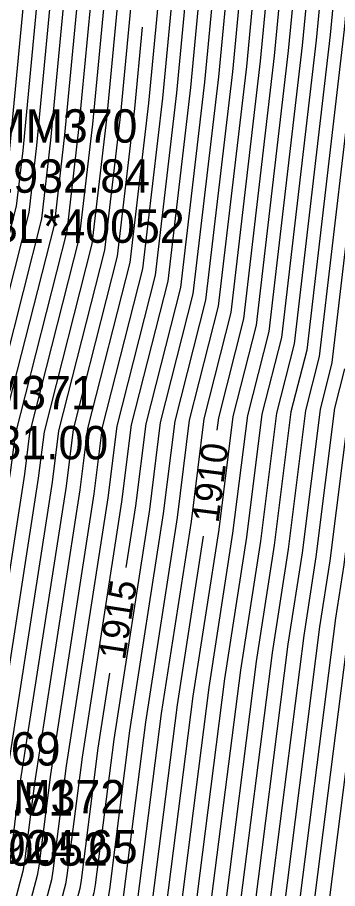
# Model space of a CAD drawing. Extents: x 1004378 to 1005103, y 553854 to 554288.
# Drawn here: x 1004966.5 to 1004990.4, y 553915.8 to 553981 of the extents above; entities that cross this region are included whole.
import ezdxf

# ---------------------------------------------------------------- set-up
doc = ezdxf.new("R2010")
doc.units = 0
for name, color, linetype in [('DTM Contours Major', 7, 'Continuous'), ('DTM Contours Major Text', 7, 'Continuous'), ('DTM Contours Minor', 7, 'Continuous'), ('Exist DTM Breakline Cogo Comment', 7, 'Continuous'), ('Exist DTM Breakline Cogo Elevation', 7, 'Continuous'), ('Exist DTM Breakline Cogo Number', 7, 'Continuous')]:
    doc.layers.add(name, color=color, linetype=linetype)

msp = doc.modelspace()

# ---------------------------------------------------------------- linework, layer by layer
at = {"layer": 'DTM Contours Major'}
for points in [[(1004990.518, 554049.324), (1004989.746, 554042.345), (1004988.945, 554039.431), (1004989.353, 554038.463), (1004988.859, 554029.118), (1004988.632, 554018.987), (1004987.49, 553995.198), (1004986.608, 553987.828), (1004985.684, 553978.101), (1004983.38, 553958.418), (1004981.497, 553951.011), (1004981.379, 553950.073)], [(1004984.132, 554039.131), (1004983.915, 554035.018), (1004983.493, 554016.156), (1004982.562, 553996.779), (1004981.844, 553990.776), (1004980.452, 553976.132), (1004978.652, 553960.758), (1004976.062, 553950.567), (1004975.294, 553944.427), (1004974.577, 553939.804)], [(1004992.875, 554003.128), (1004992.418, 553993.617), (1004991.372, 553984.881), (1004990.915, 553980.071), (1004988.107, 553956.077), (1004986.932, 553951.455), (1004985.684, 553941.478), (1004984.331, 553932.757), (1004981.805, 553912.854), (1004981.751, 553912.525), (1004979.522, 553904.173)], [(1004971.479, 553987.875), (1004969.989, 553972.194), (1004969.198, 553965.438), (1004965.192, 553949.68), (1004964.904, 553947.376), (1004960.748, 553920.578), (1004960.368, 553920.099), (1004959.949, 553919.572), (1004959.874, 553919.536), (1004954.889, 553917.367), (1004952.025, 553915.484), (1004933.597, 553906.315), (1004932.685, 553906.503)], [(1004975.8, 553980.258), (1004975.22, 553974.163), (1004973.925, 553963.098), (1004970.627, 553950.123), (1004970.099, 553945.901), (1004966.549, 553923.013), (1004965.932, 553918.15), (1004965.808, 553917.384), (1004962.695, 553905.72), (1004954.669, 553902.046), (1004953.262, 553901.433), (1004941.713, 553893.841)], [(1004995.335, 553975.107), (1004992.834, 553953.737), (1004992.367, 553951.898), (1004990.879, 553940.003), (1004990.259, 553936.005), (1004987.096, 553911.089), (1004987.066, 553910.906), (1004985.268, 553904.169), (1004980.322, 553886.217), (1004977.192, 553877.08)], [(1004980.362, 553942.139), (1004978.404, 553929.509), (1004976.514, 553914.62), (1004976.437, 553914.145), (1004971.786, 553896.718), (1004970.051, 553890.42), (1004965.256, 553876.423), (1004947.497, 553866.765), (1004945.875, 553865.882)], [(1004973.351, 553931.899), (1004972.477, 553926.261), (1004971.223, 553916.385), (1004971.123, 553915.765), (1004965.045, 553892.992), (1004964.916, 553892.521), (1004964.557, 553891.474), (1004961.933, 553890.047), (1004946.37, 553881.961), (1004940.591, 553878.151), (1004931.906, 553872.425), (1004932.715, 553870.481)]]:
    msp.add_lwpolyline(points, dxfattribs=at)
at = {"layer": 'DTM Contours Minor'}
for points in [[(1004972.981, 554045.52), (1004972.185, 554009.926), (1004971.721, 554000.256), (1004971.362, 553997.261), (1004968.942, 553971.8), (1004968.253, 553965.906), (1004964.105, 553949.591), (1004963.865, 553947.671), (1004960.401, 553925.336), (1004957.491, 553921.673), (1004957.35, 553921.495), (1004957.063, 553921.358), (1004955.215, 553920.554), (1004954.153, 553919.855), (1004932.16, 553908.913), (1004916.353, 553912.182), (1004913.842, 553914.186), (1004913.087, 553911.609), (1004912.621, 553908.909), (1004907.637, 553886.746), (1004907.279, 553884.335), (1004906.612, 553883.292), (1004908.282, 553879.28)], [(1004975.015, 554045.638), (1004974.241, 554011.059), (1004973.692, 553999.624), (1004973.268, 553996.082), (1004971.035, 553972.588), (1004970.143, 553964.97), (1004966.279, 553949.768), (1004965.943, 553947.081), (1004961.807, 553920.414), (1004961.699, 553919.562), (1004961.557, 553918.68), (1004961.124, 553917.06), (1004960.01, 553916.55), (1004954.564, 553914.18), (1004949.897, 553911.112), (1004935.034, 553903.717), (1004920.298, 553906.764), (1004913.738, 553897.346), (1004910.842, 553884.469), (1004910.705, 553883.545), (1004910.449, 553883.146), (1004912.725, 553877.68)], [(1004976.003, 554044.458), (1004975.269, 554011.625), (1004974.678, 553999.308), (1004974.221, 553995.492), (1004972.081, 553972.981), (1004971.089, 553964.502), (1004967.366, 553949.857), (1004966.982, 553946.786), (1004962.993, 553921.064), (1004962.757, 553919.209), (1004962.62, 553918.356), (1004961.517, 553914.225), (1004958.675, 553912.924), (1004954.239, 553910.994), (1004947.768, 553906.74), (1004936.47, 553901.118), (1004925.269, 553903.435), (1004913.007, 553885.833), (1004912.444, 553883.33), (1004912.418, 553883.151), (1004912.368, 553883.073), (1004914.946, 553876.88)], [(1004976.992, 554043.278), (1004976.297, 554012.192), (1004975.663, 553998.992), (1004975.174, 553994.903), (1004973.128, 553973.375), (1004972.034, 553964.034), (1004968.453, 553949.946), (1004968.021, 553946.491), (1004964.178, 553921.714), (1004963.816, 553918.856), (1004963.683, 553918.032), (1004961.91, 553911.39), (1004957.339, 553909.298), (1004953.913, 553907.807), (1004945.64, 553902.368), (1004937.907, 553898.52), (1004930.24, 553900.106), (1004920.136, 553885.602), (1004914.696, 553882.016), (1004917.167, 553876.081)], [(1004977.981, 554042.098), (1004977.325, 554012.758), (1004976.649, 553998.676), (1004976.126, 553994.313), (1004974.174, 553973.769), (1004972.98, 553963.566), (1004969.54, 553950.035), (1004969.06, 553946.196), (1004965.364, 553922.363), (1004964.874, 553918.503), (1004964.745, 553917.708), (1004962.303, 553908.555), (1004956.004, 553905.672), (1004953.588, 553904.62), (1004943.512, 553897.997), (1004939.343, 553895.922), (1004935.21, 553896.777), (1004929.764, 553888.959), (1004917.155, 553880.646), (1004919.388, 553875.281)], [(1004971.881, 554041.705), (1004971.157, 554009.36), (1004970.735, 554000.573), (1004970.409, 553997.85), (1004967.896, 553971.406), (1004967.307, 553966.374), (1004963.018, 553949.502), (1004962.826, 553947.966), (1004960.054, 553930.094), (1004956.322, 553925.395), (1004955.382, 553924.012), (1004954.895, 553923.733), (1004952.275, 553922.234), (1004930.724, 553911.511), (1004918.442, 553914.051), (1004912.975, 553918.414), (1004911.33, 553912.804), (1004910.317, 553906.926), (1004906.034, 553887.884), (1004905.566, 553884.73), (1004904.694, 553883.365), (1004906.061, 553880.08)], [(1004979.959, 554039.738), (1004979.381, 554013.891), (1004978.62, 553998.043), (1004978.032, 553993.134), (1004976.267, 553974.557), (1004974.871, 553962.63), (1004971.714, 553950.212), (1004971.138, 553945.606), (1004967.735, 553923.663), (1004966.99, 553917.797), (1004966.871, 553917.06), (1004963.088, 553902.885), (1004953.334, 553898.42), (1004952.937, 553898.247), (1004949.019, 553895.671), (1004940.949, 553890.351), (1004922.072, 553877.905), (1004923.831, 553873.681)], [(1004988.333, 554039.04), (1004987.87, 554030.298), (1004987.604, 554018.421), (1004986.505, 553995.514), (1004985.655, 553988.418), (1004984.637, 553977.708), (1004982.434, 553958.886), (1004980.41, 553950.922), (1004979.45, 553943.247), (1004977.219, 553928.86), (1004975.456, 553914.973), (1004975.374, 553914.469), (1004970.438, 553895.973), (1004969.024, 553890.84), (1004965.116, 553879.433), (1004942.966, 553867.387), (1004942.363, 553867.059)], [(1004980.948, 554038.558), (1004980.409, 554014.457), (1004979.606, 553997.727), (1004978.985, 553992.545), (1004977.313, 553974.951), (1004975.816, 553962.162), (1004972.801, 553950.301), (1004972.177, 553945.311), (1004968.92, 553924.312), (1004968.048, 553917.444), (1004967.934, 553916.736), (1004963.481, 553900.05), (1004955.023, 553896.178), (1004951.726, 553894.465), (1004940.859, 553887.301), (1004924.53, 553876.535), (1004926.052, 553872.881)], [(1004970.78, 554037.89), (1004970.129, 554008.794), (1004969.75, 554000.889), (1004969.456, 553998.44), (1004966.85, 553971.012), (1004966.362, 553966.842), (1004961.931, 553949.413), (1004961.787, 553948.261), (1004959.707, 553934.852), (1004956.907, 553931.326), (1004954.06, 553927.139), (1004953.648, 553926.903), (1004944.652, 553921.754), (1004929.287, 553914.109), (1004920.531, 553915.92), (1004912.107, 553922.642), (1004909.573, 553913.998), (1004908.012, 553904.943), (1004904.431, 553889.023), (1004903.852, 553885.125), (1004902.775, 553883.437), (1004903.84, 553880.88)], [(1004990.374, 554037.886), (1004989.848, 554027.938), (1004989.66, 554019.554), (1004988.476, 553994.882), (1004987.561, 553987.239), (1004986.73, 553978.495), (1004984.325, 553957.95), (1004982.584, 553951.1), (1004981.528, 553942.657), (1004979.589, 553930.159), (1004977.572, 553914.267), (1004977.5, 553913.821), (1004973.135, 553897.463), (1004971.078, 553890), (1004965.395, 553873.413), (1004952.028, 553866.143), (1004949.387, 553864.706)], [(1004981.937, 554037.378), (1004981.437, 554015.023), (1004980.591, 553997.411), (1004979.938, 553991.955), (1004978.359, 553975.345), (1004976.762, 553961.694), (1004973.888, 553950.39), (1004973.216, 553945.017), (1004970.106, 553924.962), (1004969.106, 553917.091), (1004968.997, 553916.413), (1004963.874, 553897.215), (1004958.674, 553894.835), (1004949.941, 553890.297), (1004940.77, 553884.251), (1004926.989, 553875.165), (1004928.273, 553872.081)], [(1004991.395, 554037.308), (1004990.837, 554026.758), (1004990.688, 554020.12), (1004989.461, 553994.565), (1004988.514, 553986.649), (1004987.776, 553978.889), (1004985.27, 553957.481), (1004983.671, 553951.188), (1004982.567, 553942.362), (1004980.775, 553930.808), (1004978.63, 553913.914), (1004978.563, 553913.497), (1004974.483, 553898.208), (1004972.105, 553889.579), (1004965.535, 553870.402), (1004956.559, 553865.52), (1004952.898, 553863.53)], [(1004982.926, 554036.198), (1004982.465, 554015.589), (1004981.577, 553997.095), (1004980.891, 553991.365), (1004979.406, 553975.738), (1004977.707, 553961.226), (1004974.975, 553950.478), (1004974.255, 553944.722), (1004971.291, 553925.611), (1004970.165, 553916.738), (1004970.06, 553916.089), (1004964.266, 553894.38), (1004962.325, 553893.491), (1004948.155, 553886.129), (1004940.68, 553881.201), (1004929.448, 553873.795), (1004930.494, 553871.281)], [(1004992.416, 554036.731), (1004991.826, 554025.578), (1004991.716, 554020.686), (1004990.447, 553994.249), (1004989.467, 553986.06), (1004988.823, 553979.283), (1004986.216, 553957.013), (1004984.758, 553951.277), (1004983.606, 553942.067), (1004981.96, 553931.458), (1004979.688, 553913.561), (1004979.626, 553913.173), (1004975.831, 553898.953), (1004973.133, 553889.159), (1004965.675, 553867.392), (1004961.09, 553864.898), (1004956.41, 553862.353)], [(1004993.436, 554036.154), (1004992.815, 554024.398), (1004992.744, 554021.253), (1004991.433, 553993.933), (1004990.419, 553985.47), (1004989.869, 553979.677), (1004987.161, 553956.545), (1004985.845, 553951.366), (1004984.645, 553941.773), (1004983.146, 553932.108), (1004980.746, 553913.208), (1004980.689, 553912.849), (1004977.179, 553899.699), (1004974.16, 553888.739), (1004965.815, 553864.382), (1004965.62, 553864.276), (1004959.921, 553861.177)], [(1004969.679, 554034.076), (1004969.101, 554008.227), (1004968.764, 554001.205), (1004968.504, 553999.029), (1004965.804, 553970.618), (1004965.416, 553967.31), (1004960.844, 553949.324), (1004960.748, 553948.556), (1004959.36, 553939.61), (1004957.492, 553937.258), (1004952.739, 553930.265), (1004952.402, 553930.072), (1004937.029, 553921.274), (1004927.851, 553916.707), (1004922.62, 553917.789), (1004911.24, 553926.87), (1004907.816, 553915.193), (1004905.707, 553902.959), (1004902.829, 553890.161), (1004902.139, 553885.52), (1004900.857, 553883.51), (1004901.619, 553881.68)], [(1004984.903, 554033.838), (1004984.52, 554016.722), (1004983.548, 553996.462), (1004982.797, 553990.186), (1004981.498, 553976.526), (1004979.598, 553960.29), (1004977.149, 553950.656), (1004976.333, 553944.132), (1004973.662, 553926.911), (1004972.281, 553916.032), (1004972.186, 553915.441), (1004966.394, 553893.738), (1004965.943, 553892.101), (1004964.697, 553888.464), (1004955.582, 553883.507), (1004944.585, 553877.793), (1004940.501, 553875.1), (1004934.365, 553871.055), (1004934.936, 553869.681)], [(1004985.892, 554032.658), (1004985.548, 554017.288), (1004984.533, 553996.146), (1004983.749, 553989.597), (1004982.545, 553976.92), (1004980.543, 553959.822), (1004978.236, 553950.745), (1004977.372, 553943.837), (1004974.848, 553927.56), (1004973.339, 553915.679), (1004973.248, 553915.117), (1004967.742, 553894.483), (1004966.97, 553891.681), (1004964.836, 553885.454), (1004949.23, 553876.966), (1004942.8, 553873.625), (1004940.412, 553872.05), (1004936.823, 553869.685), (1004937.157, 553868.881)], [(1004986.881, 554031.478), (1004986.576, 554017.855), (1004985.519, 553995.83), (1004984.702, 553989.007), (1004983.591, 553977.314), (1004981.489, 553959.354), (1004979.323, 553950.833), (1004978.411, 553943.542), (1004976.033, 553928.21), (1004974.397, 553915.326), (1004974.311, 553914.793), (1004969.09, 553895.228), (1004967.997, 553891.26), (1004964.976, 553882.444), (1004942.879, 553870.426), (1004941.014, 553869.457), (1004940.322, 553869), (1004939.282, 553868.314), (1004939.379, 553868.082)], [(1004993.008, 553980.858), (1004989.998, 553955.141), (1004989.106, 553951.632), (1004987.762, 553940.888), (1004986.702, 553934.057), (1004983.921, 553912.148), (1004983.877, 553911.878), (1004981.224, 553901.934), (1004977.241, 553887.478), (1004970.741, 553868.507), (1004968.428, 553861.755), (1004970.077, 553861.893), (1004972.539, 553861.906)], [(1004991.962, 553980.464), (1004989.052, 553955.609), (1004988.019, 553951.543), (1004986.723, 553941.183), (1004985.517, 553933.407), (1004982.863, 553912.501), (1004982.814, 553912.201), (1004979.875, 553901.189), (1004976.214, 553887.898), (1004969.077, 553867.067), (1004966.536, 553859.651), (1004966.868, 553859.679), (1004967.364, 553859.682)], [(1004990.943, 553954.673), (1004990.193, 553951.721), (1004988.801, 553940.593), (1004987.888, 553934.706), (1004984.979, 553911.795), (1004984.94, 553911.554), (1004982.572, 553902.679), (1004978.268, 553887.058), (1004972.406, 553869.948), (1004970.32, 553863.858), (1004973.285, 553864.107), (1004977.713, 553864.13)], [(1004991.28, 553951.81), (1004989.84, 553940.298), (1004989.073, 553935.356), (1004986.037, 553911.442), (1004986.003, 553911.23), (1004983.92, 553903.424), (1004979.295, 553886.637), (1004974.071, 553871.389), (1004972.211, 553865.961), (1004976.494, 553866.321), (1004982.888, 553866.354)], [(1004992.63, 553937.305), (1004989.212, 553910.383), (1004989.192, 553910.258), (1004987.965, 553905.66), (1004982.377, 553885.376), (1004979.065, 553875.712), (1004977.887, 553872.272), (1004986.12, 553872.962), (1004998.411, 553873.026)], [(1004991.444, 553936.655), (1004988.154, 553910.736), (1004988.129, 553910.582), (1004986.616, 553904.915), (1004981.349, 553885.797), (1004977.401, 553874.271), (1004975.995, 553870.168), (1004982.911, 553870.748), (1004993.236, 553870.802)]]:
    msp.add_lwpolyline(points, dxfattribs=at)

# ---------------------------------------------------------------- texts
at = {"layer": 'DTM Contours Major Text'}
for s, rotation, p in [('1910', 82.69703, (1004981.503, 553943.08)), ('1915', 81.18535, (1004974.504, 553932.812))]:
    msp.add_text(s, height=2, rotation=rotation, dxfattribs=at).set_placement(p)
at = {"layer": 'Exist DTM Breakline Cogo Comment'}
for s, p in [('BL*40052', (1004964.287, 553964.107)), ('EL*40052', (1004958.533, 553917.471))]:
    msp.add_text(s, height=2.5, dxfattribs=at).set_placement(p)
at = {"layer": 'Exist DTM Breakline Cogo Elevation'}
for s, p in [('1932.84', (1004964.287, 553967.857)), ('1931.00', (1004961.165, 553947.897)), ('1926.51', (1004958.533, 553921.221)), ('1924.65', (1004963.371, 553917.639))]:
    msp.add_text(s, height=2.5, dxfattribs=at).set_placement(p)
at = {"layer": 'Exist DTM Breakline Cogo Number'}
for s, p in [('MM370', (1004964.287, 553971.607)), ('MM371', (1004961.165, 553951.647)), ('MM369', (1004958.533, 553924.971)), ('MM372', (1004963.371, 553921.389))]:
    msp.add_text(s, height=2.5, dxfattribs=at).set_placement(p)

doc.saveas('drawing.dxf')
